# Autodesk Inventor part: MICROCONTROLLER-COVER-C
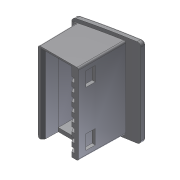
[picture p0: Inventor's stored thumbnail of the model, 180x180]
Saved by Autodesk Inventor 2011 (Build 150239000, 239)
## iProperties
Created: 2010-06
Part Number: MICROCONTROLLER-COVER-C
Document SubType Name: Modeling
Designer: kurdi
Density: 1 g/cm^3
Author: kurdi
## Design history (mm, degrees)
feature "Base1"
node "NONE"
